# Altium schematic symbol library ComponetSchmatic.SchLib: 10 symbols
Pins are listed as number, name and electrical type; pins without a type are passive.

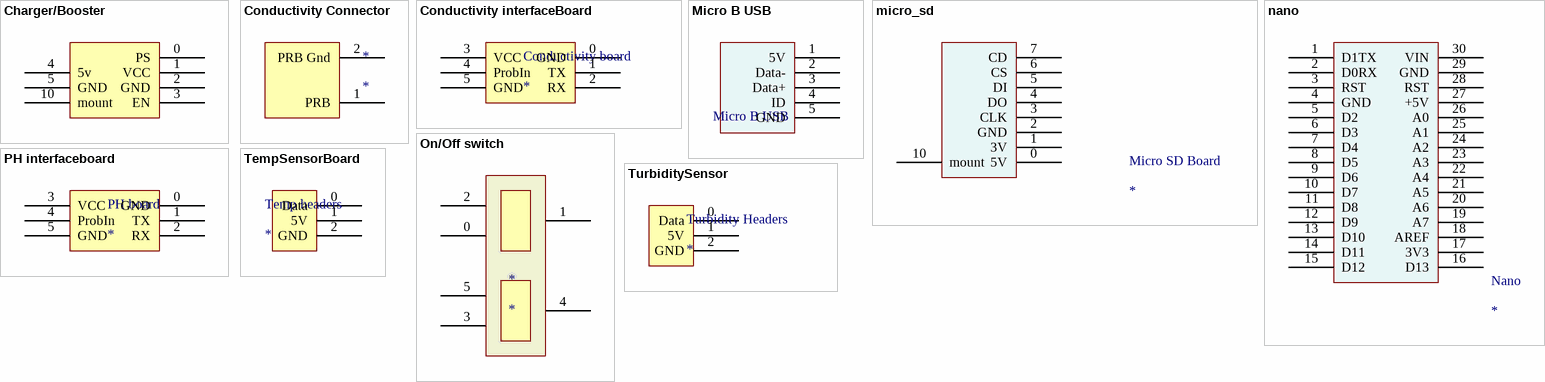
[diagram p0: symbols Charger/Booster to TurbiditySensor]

## Charger/Booster
designator Charger  (value not drawn)
footprint CHARGER/BOOSTER
pins: 0 PS, 1 VCC, 2 GND, 3 EN, 4 5v, 5 GND, 10 mount "just to provide mount holes"

## Conductivity Connector
designator *
footprint Conductivity Connector (no BNC)
pins: 1 PRB, 2 PRB Gnd

## Conductivity interfaceBoard
designator Conductivity board
footprint CONDUCTIVITY INTERFACE BOARD - duplicate
pins: 0 GND, 1 TX, 2 RX, 3 VCC, 4 ProbIn, 5 GND

## Micro B USB
designator Micro B USB  (value not drawn)
footprint Micro USB B
pins: 1 5V, 2 Data-, 3 Data+, 4 ID, 5 GND

## micro_sd
designator Micro SD Board
footprint Micro SD
pins: 0 5V, 1 3V, 2 GND, 3 CLK, 4 DO, 5 DI, 6 CS, 7 CD, 10 mount "just to get the mount holes to show up properly"

## nano
designator Nano
footprint NANO
pins: 1 D1TX, 2 D0RX, 3 RST, 4 GND, 5 D2, 6 D3, 7 D4, 8 D5, 9 D6, 10 D7, 11 D8, 12 D9, 13 D10, 14 D11, 15 D12, 16 D13, 17 3V3, 18 AREF, 19 A7, 20 A6, 21 A5, 22 A4, 23 A3, 24 A2, 25 A1, 26 A0, 27 +5V, 28 RST, 29 GND, 30 VIN

## On/Off switch
designator *
footprint On/Off Switch (DPDT toggle switch)
pins: 0, 1, 2, 3, 4, 5

## PH interfaceboard
designator PH board
footprint PH INTERFACE BOARD
pins: 0 GND, 1 TX, 2 RX, 3 VCC, 4 ProbIn, 5 GND

## TempSensorBoard
designator Temp headers
footprint TEMP HEADER
footprint Model Name (Footprint not found)
pins: 0 Data, 1 5V, 2 GND

## TurbiditySensor
designator Turbidity Headers
footprint TURBIDTY HEADER
pins: 0 Data, 1 5V, 2 GND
